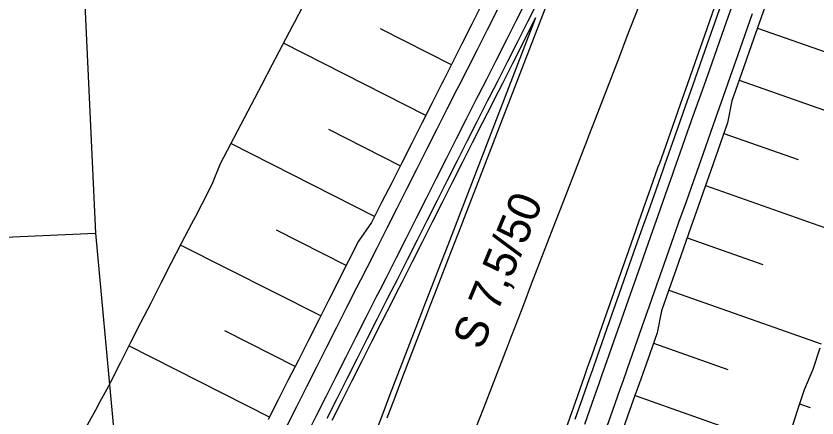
# Model space of a CAD drawing. Extents: x -439815 to -439102, y -1131353 to -1129707.
# Drawn here: x -439629.64 to -439592.68, y -1130366.92 to -1130348.38 of the extents above; entities that cross this region are included whole.
import ezdxf

# ---------------------------------------------------------------- set-up
doc = ezdxf.new("R2010")
doc.units = 0
for name, color, linetype in [('Level 15', 7, 'Continuous'), ('Level 17', 7, 'Continuous'), ('Level 2', 7, 'Continuous'), ('Level 8', 7, 'Continuous')]:
    doc.layers.add(name, color=color, linetype=linetype)

msp = doc.modelspace()

# ---------------------------------------------------------------- linework, layer by layer
at = {"layer": 'Level 15'}
for p, q in [((-439595.418, -1130348.935), (-439591.938, -1130350.161)), ((-439609.549, -1130350.629), (-439612.824, -1130348.971)), ((-439610.729, -1130352.962), (-439617.301, -1130349.635)), ((-439596.268, -1130351.345), (-439589.241, -1130353.817)), ((-439611.91, -1130355.295), (-439615.212, -1130353.623)), ((-439596.972, -1130353.794), (-439593.544, -1130355.004)), ((-439613.09, -1130357.627), (-439619.726, -1130354.267)), ((-439597.821, -1130356.204), (-439590.902, -1130358.643)), ((-439614.399, -1130359.883), (-439617.622, -1130358.255)), ((-439598.67, -1130358.613), (-439595.18, -1130359.843)), ((-439615.58, -1130362.216), (-439622.054, -1130358.944)), ((-439599.52, -1130361.023), (-439592.479, -1130363.502)), ((-439616.76, -1130364.548), (-439620.004, -1130362.909)), ((-439617.941, -1130366.881), (-439624.434, -1130363.6)), ((-439600.224, -1130363.472), (-439596.792, -1130364.684)), ((-439601.073, -1130365.882), (-439594.152, -1130368.324)), ((-439593.481, -1130366.268), (-439592.991, -1130366.447))]:
    msp.add_line(p, q, dxfattribs=at)
at = {"layer": 'Level 17'}
msp.add_line((-439626.796, -1130340.856), (-439625.968, -1130358.394), dxfattribs=at)
msp.add_lwpolyline([(-439630.844, -1130358.608), (-439625.968, -1130358.394), (-439624.666, -1130372.546)], dxfattribs=at)
at = {"layer": 'Level 8'}
for points in [[(-439604.53, -1130346.222), (-439609.222, -1130358.36), (-439609.59, -1130359.312), (-439609.958, -1130360.263), (-439610.326, -1130361.215), (-439610.552, -1130361.801), (-439610.693, -1130362.167), (-439611.061, -1130363.119), (-439611.429, -1130364.071), (-439611.797, -1130365.022), (-439612.165, -1130365.974), (-439612.533, -1130366.926)], [(-439600.708, -1130347.429), (-439601.076, -1130348.381), (-439601.444, -1130349.332), (-439601.812, -1130350.284), (-439602.18, -1130351.236), (-439602.548, -1130352.188), (-439602.916, -1130353.14), (-439603.216, -1130353.916), (-439603.284, -1130354.091), (-439603.651, -1130355.043), (-439604.019, -1130355.995), (-439604.387, -1130356.947), (-439604.755, -1130357.898), (-439605.123, -1130358.85), (-439605.491, -1130359.802), (-439605.859, -1130360.754), (-439606.227, -1130361.706), (-439606.595, -1130362.657), (-439606.821, -1130363.243), (-439606.962, -1130363.609), (-439607.33, -1130364.561), (-439607.698, -1130365.513), (-439608.066, -1130366.464), (-439608.434, -1130367.416)], [(-439606.082, -1130347.647), (-439606.545, -1130348.562), (-439607.008, -1130349.477), (-439607.471, -1130350.392), (-439607.934, -1130351.307), (-439608.312, -1130352.053), (-439608.397, -1130352.222), (-439608.861, -1130353.137), (-439609.324, -1130354.052), (-439609.787, -1130354.967), (-439610.25, -1130355.882), (-439610.713, -1130356.797), (-439611.176, -1130357.712), (-439611.639, -1130358.627), (-439612.102, -1130359.542), (-439612.565, -1130360.457), (-439612.85, -1130361.02), (-439613.028, -1130361.372), (-439613.491, -1130362.287), (-439613.954, -1130363.202), (-439614.417, -1130364.117), (-439614.88, -1130365.032), (-439615.343, -1130365.947), (-439615.806, -1130366.862), (-439616.27, -1130367.777)], [(-439605.575, -1130347.736), (-439606.038, -1130348.651), (-439606.501, -1130349.566), (-439606.964, -1130350.481), (-439607.427, -1130351.396), (-439607.805, -1130352.142), (-439607.89, -1130352.311), (-439608.353, -1130353.226), (-439608.817, -1130354.141), (-439609.28, -1130355.056), (-439609.743, -1130355.971), (-439610.206, -1130356.886), (-439610.669, -1130357.801), (-439611.132, -1130358.716), (-439611.595, -1130359.631), (-439612.058, -1130360.546), (-439612.343, -1130361.109), (-439612.521, -1130361.461), (-439612.984, -1130362.376), (-439613.447, -1130363.291), (-439613.91, -1130364.206), (-439614.373, -1130365.121), (-439614.836, -1130366.036), (-439615.299, -1130366.951)], [(-439597.298, -1130347.653), (-439597.637, -1130348.616), (-439597.977, -1130349.579), (-439598.316, -1130350.541), (-439598.655, -1130351.504), (-439598.995, -1130352.467), (-439599.334, -1130353.43), (-439599.673, -1130354.393), (-439599.95, -1130355.178), (-439600.013, -1130355.356), (-439600.352, -1130356.318), (-439600.691, -1130357.281), (-439601.031, -1130358.244), (-439601.37, -1130359.207), (-439601.709, -1130360.17), (-439602.049, -1130361.132), (-439602.388, -1130362.095), (-439602.727, -1130363.058), (-439603.067, -1130364.021), (-439603.276, -1130364.614), (-439603.406, -1130364.984), (-439603.745, -1130365.947), (-439604.085, -1130366.909), (-439604.424, -1130367.872)], [(-439597.065, -1130347.743), (-439597.404, -1130348.706), (-439597.744, -1130349.669), (-439598.083, -1130350.632), (-439598.422, -1130351.594), (-439598.762, -1130352.557), (-439599.101, -1130353.52), (-439599.44, -1130354.483), (-439599.717, -1130355.268), (-439599.78, -1130355.446), (-439600.119, -1130356.409), (-439600.458, -1130357.371), (-439600.798, -1130358.334), (-439601.137, -1130359.297), (-439601.476, -1130360.26), (-439601.815, -1130361.223), (-439602.155, -1130362.185), (-439602.494, -1130363.148), (-439602.833, -1130364.111), (-439603.042, -1130364.704), (-439603.173, -1130365.074), (-439603.512, -1130366.037), (-439603.851, -1130367)], [(-439594.907, -1130347.483), (-439595.246, -1130348.446), (-439595.585, -1130349.409), (-439595.925, -1130350.372), (-439596.264, -1130351.335), (-439596.603, -1130352.297), (-439596.803, -1130353.314), (-439597.142, -1130354.277), (-439597.481, -1130355.24), (-439597.758, -1130356.025), (-439597.821, -1130356.203), (-439598.16, -1130357.166), (-439598.499, -1130358.128), (-439598.839, -1130359.091), (-439599.178, -1130360.054), (-439599.517, -1130361.017), (-439599.857, -1130361.98), (-439600.056, -1130362.997), (-439600.395, -1130363.959), (-439600.735, -1130364.922), (-439600.944, -1130365.515), (-439601.074, -1130365.885), (-439601.413, -1130366.848), (-439601.753, -1130367.811)], [(-439616.412, -1130347.923), (-439616.793, -1130348.668), (-439616.881, -1130348.836), (-439617.358, -1130349.745), (-439617.835, -1130350.655), (-439618.312, -1130351.565), (-439618.788, -1130352.474), (-439619.264, -1130353.384), (-439619.74, -1130354.294), (-439620.216, -1130355.205), (-439620.597, -1130356.151), (-439621.072, -1130357.062), (-439621.364, -1130357.622), (-439621.547, -1130357.972), (-439622.021, -1130358.882), (-439622.496, -1130359.793), (-439622.962, -1130360.707), (-439623.427, -1130361.621), (-439623.892, -1130362.535), (-439624.357, -1130363.449), (-439624.822, -1130364.364), (-439625.287, -1130365.278), (-439625.394, -1130365.482)], [(-439608.137, -1130347.839), (-439608.6, -1130348.754), (-439609.063, -1130349.669), (-439609.526, -1130350.584), (-439609.904, -1130351.331), (-439609.989, -1130351.499), (-439610.452, -1130352.414), (-439610.915, -1130353.329), (-439611.378, -1130354.244), (-439611.841, -1130355.159), (-439612.304, -1130356.074), (-439612.768, -1130356.989), (-439613.231, -1130357.904), (-439613.834, -1130358.765), (-439614.297, -1130359.68), (-439614.582, -1130360.244), (-439614.76, -1130360.595), (-439615.223, -1130361.51), (-439615.686, -1130362.425), (-439616.149, -1130363.34), (-439616.612, -1130364.255), (-439617.075, -1130365.17), (-439617.538, -1130366.085), (-439618.001, -1130367)], [(-439607.437, -1130348.11), (-439607.9, -1130349.025), (-439608.363, -1130349.94), (-439608.826, -1130350.855), (-439609.204, -1130351.601), (-439609.29, -1130351.77), (-439609.753, -1130352.685), (-439610.216, -1130353.6), (-439610.679, -1130354.515), (-439611.142, -1130355.43), (-439611.605, -1130356.345), (-439612.068, -1130357.26), (-439612.531, -1130358.175), (-439612.994, -1130359.09), (-439613.457, -1130360.005), (-439613.742, -1130360.568), (-439613.92, -1130360.92), (-439614.383, -1130361.835), (-439614.846, -1130362.75), (-439615.309, -1130363.665), (-439615.772, -1130364.58), (-439616.236, -1130365.495), (-439616.699, -1130366.41), (-439617.162, -1130367.325)], [(-439603.396, -1130367.208), (-439603.056, -1130366.245), (-439602.717, -1130365.283), (-439602.586, -1130364.912), (-439602.378, -1130364.32), (-439602.038, -1130363.357), (-439601.699, -1130362.394), (-439601.36, -1130361.431), (-439601.02, -1130360.468), (-439600.681, -1130359.506), (-439600.342, -1130358.543), (-439600.002, -1130357.58), (-439599.663, -1130356.617), (-439599.324, -1130355.654), (-439599.261, -1130355.476), (-439598.984, -1130354.692), (-439598.645, -1130353.729), (-439598.306, -1130352.766), (-439597.966, -1130351.803), (-439597.627, -1130350.84), (-439597.288, -1130349.877), (-439596.948, -1130348.915), (-439596.609, -1130347.952)], [(-439605.665, -1130348.464), (-439606.731, -1130350.571), (-439607.194, -1130351.486), (-439607.572, -1130352.232), (-439607.657, -1130352.401), (-439608.12, -1130353.316), (-439608.583, -1130354.231), (-439609.046, -1130355.146), (-439609.51, -1130356.061), (-439609.973, -1130356.976), (-439610.436, -1130357.891), (-439610.899, -1130358.806), (-439611.362, -1130359.721), (-439611.825, -1130360.636), (-439612.11, -1130361.199), (-439612.288, -1130361.551), (-439612.751, -1130362.466), (-439613.214, -1130363.381), (-439613.677, -1130364.296), (-439614.14, -1130365.211), (-439614.603, -1130366.126), (-439615.066, -1130367.041)], [(-439605.665, -1130348.464), (-439609.455, -1130358.27), (-439609.823, -1130359.222), (-439610.191, -1130360.173), (-439610.559, -1130361.125), (-439610.785, -1130361.711), (-439610.927, -1130362.077), (-439611.294, -1130363.029), (-439611.662, -1130363.98), (-439612.03, -1130364.932), (-439612.398, -1130365.884), (-439612.766, -1130366.836), (-439613.134, -1130367.788)], [(-439595.666, -1130348.284), (-439596.005, -1130349.247), (-439596.344, -1130350.21), (-439596.684, -1130351.172), (-439597.023, -1130352.135), (-439597.362, -1130353.098), (-439597.702, -1130354.061), (-439598.041, -1130355.024), (-439598.318, -1130355.809), (-439598.38, -1130355.986), (-439598.72, -1130356.949), (-439599.059, -1130357.912), (-439599.398, -1130358.875), (-439599.738, -1130359.838), (-439600.077, -1130360.801), (-439600.416, -1130361.763), (-439600.756, -1130362.726), (-439601.095, -1130363.689), (-439601.434, -1130364.652), (-439601.643, -1130365.244), (-439601.774, -1130365.615), (-439602.113, -1130366.578), (-439602.452, -1130367.54)], [(-439592.547, -1130363.711), (-439592.863, -1130364.683), (-439593.27, -1130365.62), (-439593.586, -1130366.591), (-439593.903, -1130367.563)], [(-439625.394, -1130365.482), (-439625.774, -1130366.184), (-439625.978, -1130366.56), (-439626.264, -1130367.088), (-439626.754, -1130367.993), (-439627.243, -1130368.898), (-439627.712, -1130369.811), (-439628.146, -1130370.737), (-439628.58, -1130371.663), (-439629.014, -1130372.589), (-439629.445, -1130373.517), (-439629.876, -1130374.444), (-439630.384, -1130375.342), (-439630.469, -1130375.545), (-439630.778, -1130376.284), (-439631.171, -1130377.226), (-439631.657, -1130378.132), (-439631.833, -1130378.553), (-439633.954, -1130384.919), (-439637.976, -1130394.085), (-439638.975, -1130396.684), (-439641.049, -1130401.794), (-439641.748, -1130403.348), (-439643.691, -1130407.865)]]:
    msp.add_lwpolyline(points, dxfattribs=at)

# ---------------------------------------------------------------- texts
at = {"layer": 'Level 2'}
msp.add_text('S 7,5/50', height=1.5, rotation=67.5206, dxfattribs=at).set_placement((-439608.155, -1130363.841))

doc.saveas('drawing.dxf')
